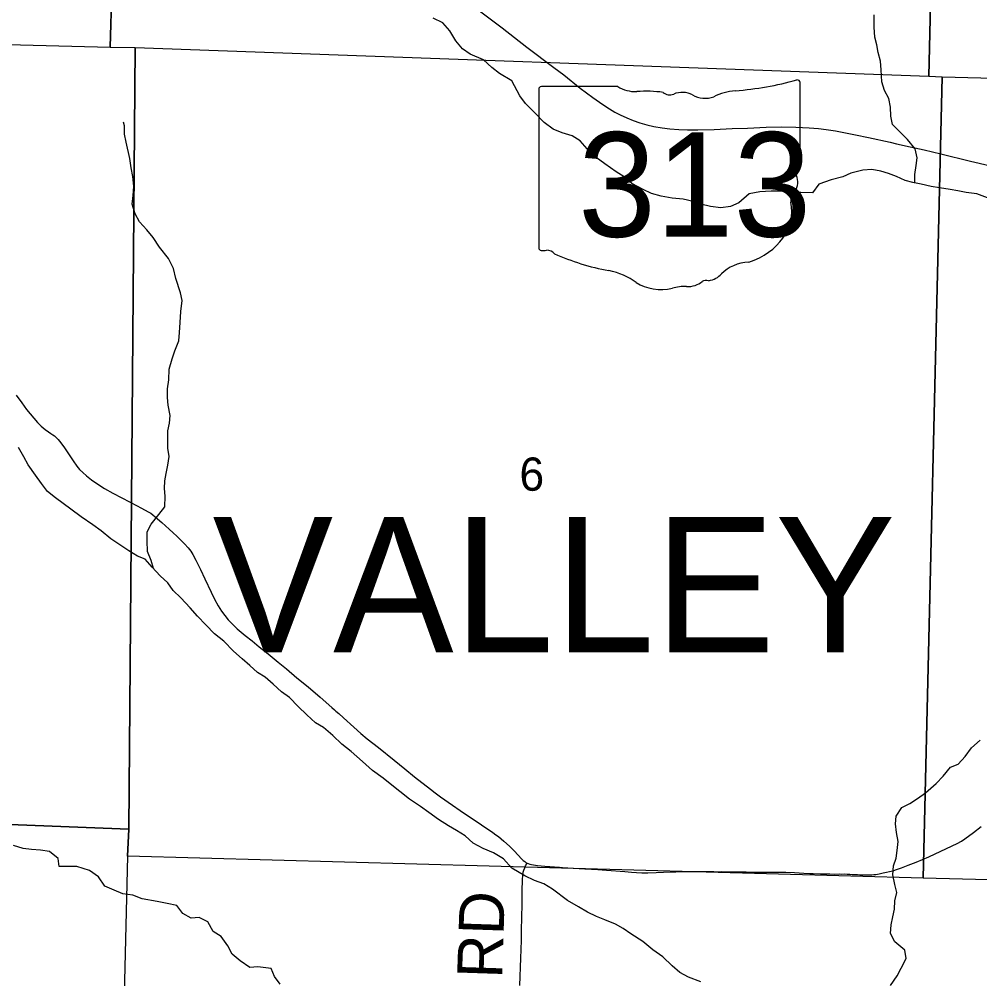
# Model space of a CAD drawing. Extents: x 0 to 34, y 0 to 22.
# Drawn here: x 26.994 to 28.206, y 19.507 to 20.718 of the extents above; entities that cross this region are included whole.
import ezdxf

# ---------------------------------------------------------------- set-up
doc = ezdxf.new("R2010")
doc.units = 0
for name, color, linetype in [('GM_X_Corporation', 7, 'Continuous'), ('GM_X_Minor_River', 7, 'Continuous'), ('GM_X_Section_Text', 7, 'Continuous'), ('GM_X_State_Location', 7, 'Continuous'), ('GM_X_State_Route', 7, 'Continuous'), ('GM_X_State_Shield', 7, 'Continuous'), ('GM_X_Township_Road', 7, 'Continuous'), ('GM_X_Township_Road_Text', 7, 'Continuous'), ('GM_X_Township_Text', 7, 'Continuous')]:
    doc.layers.add(name, color=color, linetype=linetype)

msp = doc.modelspace()

# ---------------------------------------------------------------- linework, layer by layer
at = {"layer": 'GM_X_Corporation'}
for points in [[(27.1148, 20.9), (26.1019, 20.9), (26.0969, 20.7089), (26.1216, 20.708), (27.1086, 20.6823)], [(28.1474, 20.9), (27.1148, 20.9), (27.1086, 20.6823), (27.14, 20.6818), (28.1412, 20.646)], [(29.1717, 20.9), (28.1474, 20.9), (28.1412, 20.646), (28.1583, 20.645), (29.1631, 20.6187)], [(26.1216, 20.708), (27.1086, 20.6823), (27.14, 20.6818), (27.1321, 19.6957), (26.1009, 19.7362)], [(28.1412, 20.646), (28.1583, 20.645), (28.1343, 19.6338), (27.1305, 19.6616), (27.1321, 19.6957), (27.14, 20.6818)], [(28.1583, 20.645), (29.1631, 20.6187), (29.1414, 19.6082), (28.1343, 19.6338)], [(27.1321, 19.6957), (27.1305, 19.6616), (27.1072, 18.6988), (26.0916, 18.7368), (26.1009, 19.7362)]]:
    msp.add_lwpolyline(points, close=True, dxfattribs=at)
at = {"layer": 'GM_X_Minor_River'}
for points in [[(28.1239, 20.5109), (28.1239, 20.5218), (28.1253, 20.5332), (28.1267, 20.5427), (28.124, 20.554), (28.1144, 20.5657), (28.0954, 20.5848), (28.0934, 20.5954), (28.0929, 20.6067), (28.0909, 20.6177), (28.0855, 20.6279), (28.082, 20.6388), (28.0811, 20.6536), (28.0803, 20.6646), (28.0775, 20.6756), (28.0756, 20.6854), (28.0732, 20.6952), (28.0723, 20.7077), (28.0726, 20.7233)], [(28.043, 20.5232), (28.0328, 20.5186), (28.0181, 20.515), (28.0026, 20.5095), (27.9948, 20.4988), (27.9801, 20.499), (27.9695, 20.4989), (27.9581, 20.5007), (27.9426, 20.5005), (27.9283, 20.5), (27.9147, 20.4972), (27.9015, 20.4861), (27.891, 20.4814), (27.8789, 20.4798), (27.8661, 20.4812), (27.8536, 20.4844), (27.8441, 20.4878), (27.8316, 20.4907), (27.8176, 20.492), (27.8039, 20.4942), (27.7914, 20.4978), (27.7808, 20.503), (27.7668, 20.5104), (27.7569, 20.5187), (27.747, 20.525), (27.7325, 20.5351), (27.7219, 20.5433), (27.7104, 20.5542), (27.7013, 20.5643), (27.6914, 20.5707), (27.6789, 20.5743), (27.6675, 20.5791), (27.6561, 20.5873), (27.6446, 20.599), (27.6324, 20.6113), (27.6252, 20.6211), (27.6152, 20.64), (27.5996, 20.6493), (27.5901, 20.6568), (27.5794, 20.6665), (27.5627, 20.6735), (27.5532, 20.6802), (27.5448, 20.6904), (27.5371, 20.7028), (27.5283, 20.7133), (27.5162, 20.7189)], [(27.1632, 20.0245), (27.1601, 20.0348), (27.1558, 20.0462), (27.1553, 20.0594), (27.1552, 20.0708), (27.1601, 20.0807), (27.1698, 20.0929), (27.1776, 20.1025), (27.1779, 20.1157), (27.1771, 20.1256), (27.1777, 20.1351), (27.1792, 20.1446), (27.1813, 20.1548), (27.1828, 20.1658), (27.1812, 20.1764), (27.1814, 20.1874), (27.1813, 20.1984), (27.1835, 20.2079), (27.1842, 20.2177), (27.1818, 20.2306), (27.181, 20.2405), (27.1809, 20.2511), (27.1827, 20.2628), (27.1829, 20.2761), (27.1866, 20.289), (27.1903, 20.2993), (27.1951, 20.3119), (27.1961, 20.3225), (27.1968, 20.335), (27.1978, 20.349), (27.1992, 20.3627), (27.1972, 20.3725), (27.1914, 20.3906), (27.1886, 20.4031), (27.1821, 20.4156), (27.171, 20.4302), (27.1629, 20.4423), (27.1549, 20.452), (27.1454, 20.4618), (27.14, 20.4723), (27.1361, 20.4844), (27.1375, 20.4954), (27.1382, 20.5064), (27.1373, 20.5193), (27.1349, 20.5303), (27.1333, 20.542), (27.1286, 20.5624), (27.1266, 20.5726), (27.1265, 20.5832), (27.1253, 20.5878)], [(28.2156, 20.4921), (28.202, 20.4972), (28.1883, 20.499), (28.1781, 20.5011), (28.1683, 20.5029), (28.155, 20.5047), (28.1444, 20.5065), (28.1316, 20.5094), (28.121, 20.5115), (28.1115, 20.5141), (28.1005, 20.5193), (28.0906, 20.523), (28.0808, 20.5259), (28.0694, 20.528), (28.0581, 20.5272), (28.043, 20.5232)], [(27.3039, 19.8874), (27.2944, 19.8934), (27.2849, 19.902), (27.275, 19.9106), (27.2643, 19.9204), (27.2521, 19.9327), (27.2403, 19.9421), (27.2292, 19.9533), (27.2186, 19.9646), (27.2094, 19.9751), (27.1979, 19.9875), (27.188, 19.9969), (27.1811, 20.0066), (27.1716, 20.0153), (27.1617, 20.0261), (27.1525, 20.0363), (27.143, 20.04), (27.132, 20.0467), (27.1221, 20.0534), (27.1092, 20.062), (27.0974, 20.0721), (27.0868, 20.0795), (27.0719, 20.0896), (27.059, 20.0993), (27.0491, 20.1064), (27.0396, 20.1139), (27.0293, 20.1217), (27.022, 20.1319), (27.0144, 20.1424), (27.0052, 20.1552), (26.9998, 20.1654), (26.9929, 20.1774)], [(27.8539, 19.503), (27.8383, 19.5089), (27.8273, 19.5148), (27.8174, 19.5231), (27.806, 19.5347), (27.793, 19.5436), (27.7805, 19.5541), (27.7653, 19.5638), (27.7558, 19.5702), (27.7459, 19.5757), (27.7326, 19.5813), (27.722, 19.5853), (27.7106, 19.5909), (27.6996, 19.5976), (27.6855, 19.6058), (27.6665, 19.62), (27.6555, 19.6267), (27.6441, 19.6311), (27.6319, 19.6367), (27.6152, 19.6463), (27.6049, 19.6584), (27.592, 19.6658), (27.5791, 19.6713), (27.5666, 19.678), (27.5563, 19.6874), (27.5456, 19.6941), (27.5354, 19.6997), (27.5228, 19.7079), (27.5107, 19.7168), (27.5, 19.7243), (27.4863, 19.7336), (27.4741, 19.743), (27.4639, 19.7512), (27.4528, 19.7602), (27.4395, 19.7699), (27.4269, 19.7811), (27.4128, 19.7935), (27.401, 19.8028), (27.3896, 19.8137), (27.3778, 19.8238), (27.3675, 19.8298), (27.3565, 19.8399), (27.3458, 19.8504), (27.3347, 19.862), (27.3249, 19.8691), (27.3142, 19.8785), (27.3039, 19.8874)], [(28.0932, 19.4983), (28.1014, 19.5105), (28.1066, 19.5204), (28.1129, 19.5323), (28.1113, 19.5429), (28.0984, 19.5533), (28.093, 19.5639), (28.0937, 19.5749), (28.0958, 19.5851), (28.098, 19.5946), (28.0987, 19.6052), (28.1012, 19.6159), (28.0985, 19.6257), (28.0961, 19.6382), (28.0968, 19.6492), (28.1001, 19.6591), (28.1015, 19.6689), (28.1029, 19.6799), (28.1006, 19.6913), (28.0993, 19.7026), (28.1, 19.7121), (28.1075, 19.7228), (28.1173, 19.7282), (28.127, 19.7344), (28.1372, 19.7417), (28.1507, 19.7532), (28.1593, 19.7627), (28.1687, 19.7738), (28.1784, 19.7777), (28.1871, 19.7873), (28.1953, 19.7984), (28.2062, 19.808)], [(27.3232, 19.5), (27.3159, 19.5098), (27.3117, 19.52), (27.295, 19.5221), (27.2848, 19.5212), (27.2726, 19.5294), (27.2624, 19.538), (27.257, 19.5486), (27.2486, 19.5602), (27.2387, 19.5666), (27.2318, 19.5786), (27.2208, 19.5842), (27.2109, 19.5833), (27.2003, 19.5893), (27.1927, 19.5994), (27.1805, 19.6019), (27.1677, 19.6045), (27.1491, 19.6077), (27.1373, 19.6125), (27.1245, 19.6142), (27.1135, 19.6187), (27.1017, 19.6238), (27.0937, 19.6355), (27.0823, 19.6437), (27.0663, 19.6485), (27.0561, 19.6487), (27.0444, 19.6486), (27.0428, 19.6585), (27.0322, 19.6674), (27.0208, 19.6692), (27.0095, 19.6702), (26.9989, 19.6713), (26.9867, 19.6749)]]:
    msp.add_lwpolyline(points, dxfattribs=at)
at = {"layer": 'GM_X_State_Route'}
msp.add_lwpolyline([(27.5744, 20.7283), (27.6032, 20.7066), (27.6341, 20.6825), (27.6682, 20.6566), (27.6807, 20.6473), (27.7017, 20.6308), (27.7176, 20.6189), (27.7302, 20.6099), (27.7384, 20.6045), (27.7454, 20.6004), (27.7519, 20.597), (27.7604, 20.5931), (27.7684, 20.5899), (27.7766, 20.5871), (27.7855, 20.5846), (27.7945, 20.5825), (27.8049, 20.5807), (27.8147, 20.5794), (27.8258, 20.5784), (27.8369, 20.5779), (27.8499, 20.5779), (27.8704, 20.5787), (27.8934, 20.5797), (27.9126, 20.5804), (27.9362, 20.5813), (27.9555, 20.5817), (27.9735, 20.5815), (27.9903, 20.5808), (28.0021, 20.5799), (28.012, 20.5787), (28.0237, 20.5768), (28.0487, 20.5718), (28.0651, 20.5683), (28.0924, 20.5624), (28.1008, 20.5604), (28.1178, 20.5565), (28.1354, 20.5527), (28.1566, 20.5478), (28.194, 20.5387), (28.2175, 20.533)], dxfattribs=at)
at = {"layer": 'GM_X_State_Shield'}
for p, q in [((27.6494, 20.6293), (27.6494, 20.4291)), ((27.7491, 20.6327), (27.6526, 20.6327)), ((27.979, 20.533), (27.979, 20.6377)), ((27.9789, 20.533), (27.979, 20.533))]:
    msp.add_line(p, q, dxfattribs=at)
for centre, major_axis, start_param, end_param in [((27.8616, 20.9055), (0.3495, 0), 4.814394, 5.042369), ((27.9753, 20.6381), (0.00367, 0), 6.141152, 7.989035), ((27.6532, 20.6297), (0.00382, 0), 1.712693, 3.28349), ((27.7721, 20.6559), (0.037, 0), 4.042523, 4.731795), ((27.7844, 20.5204), (0.133, 0), 1.404758, 1.657858), ((27.8303, 20.6076), (0.0222, 0), 0.950623, 2.079405), ((27.9061, 20.5716), (0.0703, 0), 1.699011, 2.107814), ((27.8146, 20.6307), (0.0107, 0), 3.836095, 5.185415), ((27.859, 20.6393), (0.0267, 0), 4.081561, 5.145723), ((27.9781, 20.5253), (0.00568, 0), 1.883978, 3.671073), ((27.9751, 20.5326), (0.00393, 0), 5.05454, 6.418171), ((27.942, 20.5121), (0.0341, 0), 5.934695, 6.695948), ((27.9921, 20.4892), (0.0248, 0), 2.387724, 3.262537), ((27.8811, 20.4758), (0.0874, 0), 5.101752, 6.440018), ((27.6532, 20.4287), (0.00385, 0), 3.00124, 4.508301), ((27.6538, 20.4492), (0.0294, 0), 4.665946, 4.897461), ((27.6598, 20.4176), (0.0106, 0), 0.519207, 1.627899), ((27.7936, 20.5974), (0.2524, 0), 4.195997, 4.488961), ((27.918, 20.373), (0.0479, 0), 1.647645, 2.488434), ((27.7184, 20.3392), (0.079, 0), 0.823519, 1.323587), ((27.8573, 20.4097), (0.0282, 0), 4.937069, 5.64225), ((27.8038, 20.4166), (0.0501, 0), 4.026481, 4.996735), ((27.8364, 20.4016), (0.0267, 0), 4.691044, 5.507374), ((27.8605, 20.3822), (0.00752, 0), 1.147584, 2.315152), ((27.8327, 20.3474), (0.0412, 0), 1.495662, 1.94098)]:
    msp.add_ellipse(centre, major_axis=major_axis, ratio=0.8, start_param=start_param, end_param=end_param, dxfattribs=at)
at = {"layer": 'GM_X_Township_Road'}
for points in [[(26.9898, 20.2431), (26.9969, 20.2337), (27.0032, 20.2253), (27.0122, 20.2142), (27.0167, 20.209), (27.0215, 20.2042), (27.0267, 20.1998), (27.0307, 20.1969), (27.0337, 20.1949), (27.0364, 20.1931), (27.0382, 20.1918), (27.0398, 20.1904), (27.0414, 20.189), (27.0429, 20.1873), (27.0464, 20.1831), (27.0508, 20.177), (27.0618, 20.1605), (27.0665, 20.1539), (27.07, 20.1495), (27.0739, 20.1455), (27.0786, 20.1414), (27.085, 20.1365), (27.0942, 20.1302), (27.1016, 20.1256), (27.1118, 20.1197), (27.1233, 20.1136), (27.1426, 20.1038), (27.1473, 20.1013), (27.1529, 20.0983), (27.1565, 20.0962), (27.1597, 20.0942), (27.1624, 20.0922), (27.1654, 20.0898), (27.1738, 20.0826), (27.183, 20.0743), (27.188, 20.0697), (27.1925, 20.0654), (27.1966, 20.0616), (27.2023, 20.0559), (27.2068, 20.0508), (27.2102, 20.0464), (27.2129, 20.0422), (27.2168, 20.0351), (27.2227, 20.0235), (27.2281, 20.0116), (27.2359, 19.9947), (27.2403, 19.9858), (27.2448, 19.9776), (27.2491, 19.9708), (27.2531, 19.9653), (27.2575, 19.96), (27.2626, 19.9546), (27.2689, 19.9486), (27.2788, 19.9401), (27.2875, 19.9331), (27.2967, 19.9257), (27.3078, 19.9167), (27.3203, 19.9065), (27.3309, 19.8979), (27.3442, 19.8867), (27.3582, 19.8753), (27.3733, 19.8624), (27.3882, 19.8492), (27.3914, 19.8463), (27.3933, 19.8447), (27.3971, 19.8416), (27.4031, 19.8361), (27.4158, 19.8243), (27.4247, 19.8165), (27.4328, 19.8098), (27.447, 19.7986), (27.4668, 19.7826), (27.4802, 19.7716), (27.4924, 19.7619), (27.5125, 19.7463), (27.5185, 19.7416), (27.5252, 19.7366), (27.5404, 19.7259), (27.5502, 19.7193), (27.5769, 19.7011), (27.5914, 19.6914), (27.5951, 19.6887), (27.5983, 19.6863), (27.6051, 19.6807), (27.6124, 19.6741), (27.6187, 19.668), (27.6274, 19.6584), (27.6298, 19.656), (27.6315, 19.6547), (27.6331, 19.6536), (27.6345, 19.6529)], [(27.6345, 19.6529), (27.6361, 19.6522), (27.6381, 19.6516), (27.6402, 19.6511), (27.6476, 19.6499), (27.6568, 19.6489), (27.6754, 19.6476), (27.6791, 19.6474), (27.6927, 19.6464), (27.7076, 19.6455), (27.7237, 19.6446), (27.7349, 19.6439), (27.7577, 19.6422), (27.7664, 19.6416), (27.7725, 19.6411), (27.7793, 19.6406), (27.7818, 19.6404), (27.7867, 19.6405), (27.7972, 19.6409), (27.8065, 19.6414), (27.822, 19.642), (27.835, 19.6422), (27.8523, 19.6422), (27.8615, 19.6422), (27.87, 19.6421), (27.8737, 19.642), (27.8761, 19.642), (27.8792, 19.6421), (27.8822, 19.642), (27.8853, 19.642), (27.8889, 19.6419), (27.892, 19.6419), (27.895, 19.6418), (27.898, 19.6418), (27.9017, 19.6417), (27.9084, 19.6418), (27.9109, 19.6417), (27.917, 19.6415), (27.9288, 19.6415), (27.9511, 19.6414), (27.961, 19.6412), (27.9721, 19.6408), (27.9839, 19.6401), (27.9913, 19.6398), (27.9955, 19.6399), (28.0047, 19.6395), (28.0164, 19.6391), (28.0225, 19.639), (28.0281, 19.6392), (28.0318, 19.639), (28.0349, 19.6391), (28.0385, 19.6388), (28.0416, 19.6388), (28.0446, 19.6385), (28.0483, 19.6385), (28.0514, 19.6383), (28.0545, 19.6382), (28.0582, 19.638), (28.0643, 19.6379), (28.0695, 19.6382), (28.072, 19.6383), (28.0747, 19.6386), (28.0788, 19.6393), (28.0838, 19.6404), (28.0959, 19.6433), (28.1018, 19.6451), (28.1071, 19.647), (28.1152, 19.6501), (28.1255, 19.6541), (28.1414, 19.6607), (28.1637, 19.6713), (28.1771, 19.6777), (28.1826, 19.6807), (28.1867, 19.6833), (28.1977, 19.6914), (28.2075, 19.6992)], [(27.6252, 19.4986), (27.6268, 19.5327), (27.6272, 19.5439), (27.6276, 19.5557), (27.6277, 19.5675), (27.628, 19.5849), (27.6282, 19.6004), (27.6283, 19.6179), (27.6286, 19.6316), (27.6291, 19.6378), (27.6297, 19.6416), (27.6304, 19.6441), (27.6317, 19.647), (27.6327, 19.6493), (27.6345, 19.6529)]]:
    msp.add_lwpolyline(points, dxfattribs=at)

# ---------------------------------------------------------------- texts
at = {"layer": 'GM_X_Section_Text'}
msp.add_text('6', height=0.0419, rotation=0, dxfattribs=at).set_placement((27.6249, 20.1227))
at = {"layer": 'GM_X_State_Location'}
for s in ['s', 'r']:
    msp.add_text(s, height=0.000189, dxfattribs=at).set_placement((27.8105, 20.5159))
msp.add_text('313', height=0.000189, rotation=0, dxfattribs=at).set_placement((27.7436, 20.5021))
at = {"layer": 'GM_X_State_Shield'}
msp.add_text('313', height=0.13184, dxfattribs=at).set_placement((27.6989, 20.4432))
at = {"layer": 'GM_X_Township_Road_Text'}
msp.add_text('RD', height=0.05682, rotation=88.1088, dxfattribs=at).set_placement((27.603, 19.5067))
at = {"layer": 'GM_X_Township_Text'}
msp.add_text('VALLEY', height=0.17045, rotation=0, dxfattribs=at).set_placement((27.2378, 19.9189))

doc.saveas('drawing.dxf')
